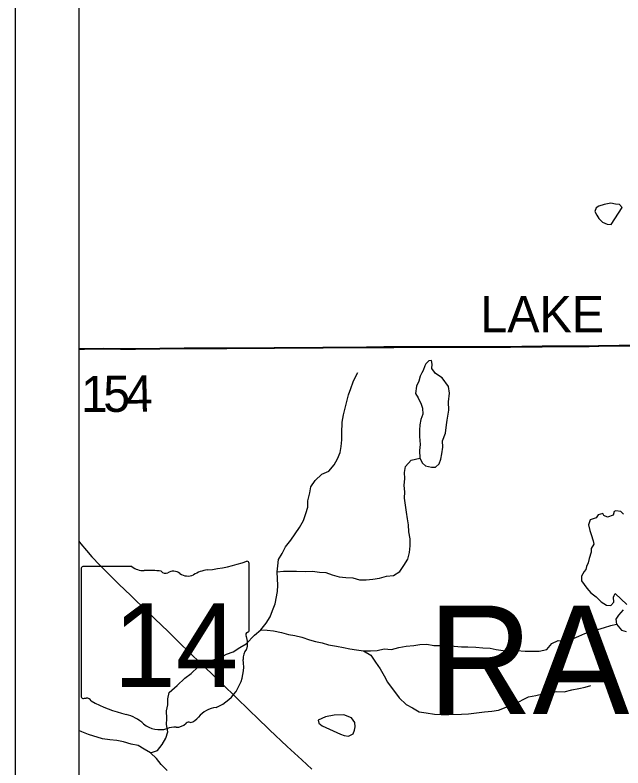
# Model space of a CAD drawing. Extents: x 0 to 34, y 0 to 22.
# Drawn here: x 13.344 to 14.299, y 14.945 to 16.128 of the extents above; entities that cross this region are included whole.
import ezdxf

# ---------------------------------------------------------------- set-up
doc = ezdxf.new("R2010")
doc.units = 0
for name, color, linetype in [('GM_X_Corporation', 7, 'Continuous'), ('GM_X_County_Road', 7, 'Continuous'), ('GM_X_County_Road_Text', 7, 'Continuous'), ('GM_X_Minor_Lake', 7, 'Continuous'), ('GM_X_Minor_River', 7, 'Continuous'), ('GM_X_State_Location', 7, 'Continuous'), ('GM_X_State_Route', 7, 'Continuous'), ('GM_X_State_Shield', 7, 'Continuous'), ('GM_X_Township_Text', 7, 'Continuous'), ('SH_Data', 7, 'Continuous')]:
    doc.layers.add(name, color=color, linetype=linetype)

msp = doc.modelspace()

# ---------------------------------------------------------------- linework, layer by layer
at = {"layer": 'GM_X_Corporation'}
for points in [[(13.4438, 19.9239), (13.4438, 15.6034), (13.4527, 15.6034), (13.482, 15.6037), (13.5093, 15.6035), (13.5329, 15.6035), (13.6093, 15.6043), (13.6304, 15.6042), (13.6379, 15.6042), (13.6763, 15.6046), (13.7509, 15.6049), (13.8273, 15.6053), (13.8956, 15.6062), (13.9229, 15.6063), (13.9385, 15.6063), (13.9664, 15.6065), (13.9973, 15.6066), (14.0165, 15.6067), (14.0401, 15.6067), (14.0568, 15.6066), (14.0935, 15.6066), (14.1096, 15.6066), (14.1152, 15.6067), (14.117, 15.6067), (14.122, 15.6067), (14.14, 15.607), (14.1716, 15.6073), (14.2057, 15.6074), (14.2243, 15.6074), (14.2454, 15.6075), (14.2603, 15.6079), (14.2926, 15.6084), (14.3323, 15.6087)], [(14.3323, 15.6087), (14.2926, 15.6084), (14.2603, 15.6079), (14.2454, 15.6075), (14.2243, 15.6074), (14.2057, 15.6074), (14.1716, 15.6073), (14.14, 15.607), (14.122, 15.6067), (14.117, 15.6067), (14.1152, 15.6067), (14.1096, 15.6066), (14.0935, 15.6066), (14.0568, 15.6066), (14.0401, 15.6067), (14.0165, 15.6067), (13.9973, 15.6066), (13.9664, 15.6065), (13.9385, 15.6063), (13.9229, 15.6063), (13.8956, 15.6062), (13.8273, 15.6053), (13.7509, 15.6049), (13.6763, 15.6046), (13.6379, 15.6042), (13.6304, 15.6042), (13.6093, 15.6043), (13.5329, 15.6035), (13.5093, 15.6035), (13.482, 15.6037), (13.4527, 15.6034), (13.4438, 15.6034), (13.4438, 13.1239)]]:
    msp.add_lwpolyline(points, dxfattribs=at)
at = {"layer": 'GM_X_County_Road'}
msp.add_lwpolyline([(13.4438, 15.6028), (13.4529, 15.6029), (13.4822, 15.6031), (13.5095, 15.6029), (13.5331, 15.603), (13.6095, 15.6037), (13.6306, 15.6037), (13.6381, 15.6037), (13.6765, 15.6041), (13.7511, 15.6043), (13.8275, 15.6047), (13.8958, 15.6057), (13.9231, 15.6057), (13.9387, 15.6057), (13.9666, 15.6059), (13.9975, 15.606), (14.0167, 15.6061), (14.0403, 15.6061), (14.057, 15.6061), (14.0937, 15.6061), (14.1098, 15.606), (14.1154, 15.6061), (14.1172, 15.6062), (14.1222, 15.6062), (14.1402, 15.6064), (14.1718, 15.6067), (14.2059, 15.6068), (14.2245, 15.6068), (14.2456, 15.607), (14.2605, 15.6073), (14.2928, 15.6079), (14.3325, 15.6082)], dxfattribs=at)
at = {"layer": 'GM_X_Minor_Lake'}
for p, q in [((14.28, 15.7985), (14.2972, 15.8256)), ((14.0156, 15.4488), (14.0151, 15.459)), ((13.826, 15.0112), (13.8549, 14.9978))]:
    msp.add_line(p, q, dxfattribs=at)
for points in [[(14.2972, 15.8256), (14.293, 15.8301), (14.287, 15.8305), (14.2794, 15.8323), (14.2692, 15.8303), (14.2605, 15.8276), (14.2564, 15.8249), (14.2545, 15.8192), (14.2576, 15.8132), (14.2607, 15.8079), (14.2664, 15.8022), (14.2736, 15.7993), (14.28, 15.7985)], [(14.0151, 15.459), (14.0199, 15.4708), (14.0213, 15.4837), (14.0224, 15.4913), (14.0249, 15.5069), (14.0245, 15.5201), (14.0262, 15.5338), (14.0247, 15.5444), (14.0147, 15.5576), (14.0041, 15.5647), (13.9983, 15.5723), (13.999, 15.5795), (13.9978, 15.5848), (13.9937, 15.5844), (13.9892, 15.5798), (13.9873, 15.5767), (13.9847, 15.5691), (13.9825, 15.5657), (13.9799, 15.5604), (13.978, 15.5528), (13.9743, 15.5448), (13.9729, 15.533), (13.9767, 15.5266), (13.9817, 15.5164), (13.9837, 15.51), (13.9841, 15.5005), (13.9812, 15.4925), (13.9797, 15.4841), (13.979, 15.4758), (13.9791, 15.4656), (13.9803, 15.453), (13.9789, 15.4436), (13.9797, 15.4318), (13.9836, 15.4239), (13.9885, 15.4194), (13.998, 15.4175), (14.0041, 15.4176), (14.0101, 15.4226), (14.0123, 15.4298), (14.0141, 15.4385), (14.0156, 15.4488)], [(14.2995, 15.3436), (14.2953, 15.3478), (14.2873, 15.3488), (14.2847, 15.3477), (14.2832, 15.342), (14.2745, 15.3389), (14.2685, 15.3415), (14.2669, 15.3445), (14.2597, 15.3426), (14.2564, 15.3376), (14.2469, 15.3345), (14.2444, 15.3269), (14.2463, 15.3178), (14.2486, 15.3114), (14.2517, 15.3019), (14.2529, 15.2966), (14.2484, 15.2894), (14.2485, 15.2837), (14.2455, 15.2738), (14.2437, 15.267), (14.2415, 15.2613), (14.2404, 15.2567), (14.2374, 15.2533), (14.2336, 15.2464), (14.2333, 15.2388), (14.2417, 15.2275), (14.2482, 15.22), (14.2566, 15.2136), (14.2646, 15.2061), (14.2726, 15.2005), (14.2794, 15.2001), (14.2843, 15.2055), (14.2835, 15.213), (14.2846, 15.2157), (14.2865, 15.2188), (14.3048, 15.2018)], [(14.2988, 15.1934), (14.2916, 15.1847), (14.2875, 15.1786), (14.2884, 15.1706), (14.2964, 15.1616), (14.3036, 15.1594)], [(13.8549, 14.9978), (13.8609, 14.9956), (13.8674, 14.9949), (13.8749, 14.9987), (13.8768, 15.004), (13.8782, 15.0097), (13.8774, 15.0162), (13.8724, 15.0237), (13.8603, 15.0282), (13.8448, 15.0277), (13.8316, 15.0253), (13.8199, 15.0199), (13.821, 15.015), (13.826, 15.0112)]]:
    msp.add_lwpolyline(points, dxfattribs=at)
at = {"layer": 'GM_X_Minor_River'}
for points in [[(13.5565, 14.9686), (13.5674, 14.9721), (13.5749, 14.9816), (13.5805, 14.9919), (13.5835, 15.0018), (13.5819, 15.0131), (13.5822, 15.0226), (13.5817, 15.0348), (13.5835, 15.0443), (13.5838, 15.0537), (13.586, 15.0636), (13.5984, 15.0743), (13.6104, 15.0858), (13.6206, 15.0935), (13.6315, 15.1038), (13.642, 15.1095), (13.6533, 15.1142), (13.6654, 15.1181), (13.676, 15.1238), (13.6866, 15.1273), (13.6971, 15.1342), (13.7069, 15.14), (13.7197, 15.1534), (13.7298, 15.1618), (13.7384, 15.1721), (13.7444, 15.1824), (13.7481, 15.1923), (13.7522, 15.2029), (13.7558, 15.2219), (13.7565, 15.2321), (13.756, 15.242), (13.7556, 15.253), (13.7566, 15.2625), (13.7577, 15.2723), (13.7633, 15.2819), (13.7685, 15.2922), (13.7771, 15.3025), (13.7839, 15.3127), (13.7906, 15.3227), (13.7966, 15.3337), (13.8007, 15.3447), (13.8036, 15.3546), (13.8035, 15.3648), (13.8068, 15.377), (13.8086, 15.3865), (13.815, 15.3964), (13.8255, 15.4064), (13.8365, 15.411), (13.8451, 15.4209), (13.8503, 15.4304), (13.8544, 15.4403), (13.8558, 15.4498), (13.8569, 15.4604), (13.8572, 15.4707), (13.8578, 15.4881), (13.8596, 15.4995), (13.8622, 15.5102), (13.8647, 15.5204), (13.8677, 15.5311), (13.8714, 15.541), (13.8751, 15.5516), (13.8796, 15.5615), (13.8822, 15.5664)], [(13.7556, 15.253), (13.7654, 15.2538), (13.7752, 15.2543), (13.7858, 15.254), (13.7995, 15.2533), (13.8112, 15.2538), (13.8222, 15.2527), (13.832, 15.2517), (13.8419, 15.2483), (13.8529, 15.2454), (13.8635, 15.244), (13.8741, 15.2437), (13.8847, 15.2403), (13.8953, 15.2404), (13.9055, 15.2416), (13.9161, 15.2432), (13.9271, 15.246), (13.9384, 15.2472), (13.9482, 15.2533), (13.9546, 15.2629), (13.9609, 15.2731), (13.9631, 15.2834), (13.9646, 15.2937), (13.9645, 15.305), (13.9625, 15.316), (13.962, 15.3266), (13.9604, 15.3365), (13.9588, 15.3467), (13.9572, 15.3577), (13.9553, 15.369), (13.9559, 15.3789), (13.9547, 15.3888), (13.9561, 15.3994), (13.9557, 15.4089), (13.9571, 15.4184), (13.9661, 15.4283), (13.9797, 15.4318)], [(13.7298, 15.1618), (13.7396, 15.1615), (13.7499, 15.1604), (13.7624, 15.1579), (13.7734, 15.1545), (13.7832, 15.1531), (13.7942, 15.1501), (13.806, 15.1461), (13.8155, 15.1435), (13.8261, 15.1413), (13.8363, 15.1383), (13.8485, 15.1362), (13.8598, 15.134), (13.8697, 15.1318), (13.8799, 15.1307), (13.8913, 15.1289), (13.9019, 15.129), (13.9125, 15.1294), (13.9234, 15.1318), (13.9348, 15.1311), (13.9465, 15.1339), (13.9582, 15.1362), (13.9699, 15.1371), (13.9798, 15.1387), (13.9904, 15.1391), (14.0014, 15.1373), (14.0142, 15.1374), (14.0335, 15.1361), (14.0449, 15.135), (14.0551, 15.1351), (14.0676, 15.1344), (14.0786, 15.1334), (14.09, 15.1331), (14.0994, 15.1309), (14.1104, 15.1294), (14.1218, 15.1291), (14.132, 15.1292), (14.1449, 15.1286), (14.1558, 15.1286), (14.1672, 15.1284), (14.1789, 15.1311), (14.1868, 15.1406), (14.197, 15.1449), (14.2076, 15.1438), (14.2181, 15.1473), (14.2291, 15.152), (14.2389, 15.1562), (14.2491, 15.1597), (14.2589, 15.1624), (14.2698, 15.1655), (14.2797, 15.1687), (14.2884, 15.1706)], [(13.8913, 15.1289), (13.9027, 15.1222), (13.91, 15.1112), (13.9172, 15.1007), (13.9234, 15.0897), (13.9288, 15.0799), (13.9471, 15.055), (13.9582, 15.0445), (13.9681, 15.0392), (13.9783, 15.0329), (13.9893, 15.0314), (14.0026, 15.0296), (14.0132, 15.029), (14.0249, 15.0291), (14.045, 15.0292), (14.0559, 15.0301), (14.0688, 15.0317), (14.0809, 15.0329), (14.0926, 15.0341), (14.1032, 15.0357), (14.1149, 15.0404), (14.1277, 15.045), (14.1504, 15.0566), (14.1617, 15.0589), (14.1726, 15.0613), (14.1832, 15.0629), (14.1946, 15.0652), (14.2063, 15.0646), (14.2184, 15.0677), (14.2294, 15.0697), (14.2392, 15.0717), (14.2482, 15.0744)], [(13.5565, 14.9686), (13.5466, 14.9746), (13.5371, 14.9802), (13.5261, 14.9824), (13.5139, 14.9861), (13.5037, 14.9879), (13.4927, 14.989), (13.481, 14.9908), (13.459, 14.9974), (13.4487, 15.0015), (13.4438, 15.0038)], [(13.5828, 14.9407), (13.5733, 14.9501), (13.566, 14.9599), (13.5565, 14.9686)]]:
    msp.add_lwpolyline(points, dxfattribs=at)
at = {"layer": 'GM_X_State_Route'}
msp.add_lwpolyline([(13.4438, 15.3012), (13.4472, 15.2969), (13.4559, 15.2864), (13.4645, 15.2767), (13.4768, 15.2636), (13.4869, 15.2534), (13.5068, 15.2338), (13.5256, 15.2156), (13.5327, 15.2088), (13.5444, 15.1976), (13.5533, 15.1889), (13.5631, 15.1794), (13.5841, 15.159), (13.5975, 15.1461), (13.6221, 15.1223), (13.6319, 15.1128), (13.6408, 15.1041), (13.6556, 15.0899), (13.6717, 15.0744), (13.689, 15.0574), (13.7134, 15.0335), (13.7233, 15.024), (13.7436, 15.0047), (13.7711, 14.9787), (13.794, 14.9577), (13.8101, 14.9431)], dxfattribs=at)
at = {"layer": 'GM_X_State_Shield'}
for p, q in [((13.5274, 15.2612), (13.4502, 15.2612)), ((13.7113, 15.1615), (13.7113, 15.2662)), ((13.4476, 15.2578), (13.4476, 15.0577)), ((13.7113, 15.1615), (13.7113, 15.1615))]:
    msp.add_line(p, q, dxfattribs=at)
for centre, radius, start, end in [((13.4506, 15.2582), 0.00305, 98.1301, 188.1301), ((13.5458, 15.2845), 0.0296, 231.6195, 271.1119), ((13.6174, 15.5341), 0.2796, 275.8445, 288.9065), ((13.7084, 15.2666), 0.00294, 351.8621, 97.738), ((13.5557, 15.1489), 0.1064, 80.4867, 94.9883), ((13.5798, 15.2593), 0.00855, 219.7921, 297.1024), ((13.5923, 15.2361), 0.0178, 54.4667, 119.1411), ((13.6153, 15.2678), 0.0214, 233.8562, 294.8282), ((13.653, 15.2001), 0.0563, 97.3462, 120.7689), ((13.7106, 15.1538), 0.00454, 107.944, 210.337), ((13.7082, 15.1611), 0.00314, 289.6038, 7.7341), ((13.6817, 15.1406), 0.0273, 340.033, 23.6496), ((13.7218, 15.1177), 0.0198, 136.8065, 186.9296), ((13.633, 15.1044), 0.0699, 292.3089, 8.9858), ((13.4507, 15.0572), 0.00308, 171.9584, 258.3066), ((13.4511, 15.0777), 0.0235, 267.339, 280.6039), ((13.456, 15.0461), 0.00848, 29.7484, 93.2717), ((13.563, 15.2259), 0.2019, 240.4129, 257.1985), ((13.6625, 15.0015), 0.0383, 94.4031, 142.5768), ((13.5028, 14.9678), 0.0632, 47.1842, 75.836), ((13.614, 15.0383), 0.0226, 282.8732, 323.2771), ((13.5711, 15.0451), 0.0401, 230.7004, 286.2918), ((13.5972, 15.0301), 0.0214, 268.777, 315.5493), ((13.6166, 15.0108), 0.00601, 65.7517, 132.6484), ((13.5943, 14.9759), 0.0329, 85.6951, 111.2099)]:
    msp.add_arc(centre, radius, start, end, dxfattribs=at)
at = {"layer": 'SH_Data'}
for p, q in [((13.3438, 20.0239), (13.3438, 13.0239)), ((13.4438, 19.9239), (13.4438, 13.1239))]:
    msp.add_line(p, q, dxfattribs=at)

# ---------------------------------------------------------------- texts
at = {"layer": 'GM_X_County_Road_Text'}
for s, height, rotation, p in [('LAKE', 0.05682, 0, (14.0746, 15.6294)), ('1', 0.0568, 0.0545, (13.4472, 15.5041)), ('5', 0.0568, 0.2253, (13.4824, 15.5042)), ('4', 0.0568, 0.9903, (13.5182, 15.5043))]:
    msp.add_text(s, height=height, rotation=rotation, dxfattribs=at).set_placement(p)
at = {"layer": 'GM_X_State_Location'}
for s in ['s', 'r']:
    msp.add_text(s, height=0.000189, dxfattribs=at).set_placement((13.5765, 15.1444))
msp.add_text('14', height=0.000189, rotation=0, dxfattribs=at).set_placement((13.5288, 15.1306))
at = {"layer": 'GM_X_State_Shield'}
msp.add_text('14', height=0.13184, dxfattribs=at).set_placement((13.4982, 15.0718))
at = {"layer": 'GM_X_Township_Text'}
msp.add_text('RAVENNA', height=0.17045, rotation=0, dxfattribs=at).set_placement((13.9921, 15.0296))

doc.saveas('drawing.dxf')
